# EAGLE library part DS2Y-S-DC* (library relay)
MINIATURE RELAY NAiS Source: http://www.mew-europe.com/.. en_ds_61005_0023.pdf
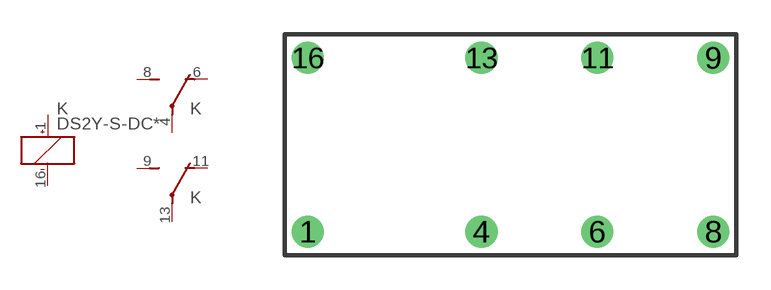
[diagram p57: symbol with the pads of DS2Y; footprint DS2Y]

Designator prefix K; gates 1=K+- 2=U 3=U

## DS2Y-S-DC1.5V (MPN: DS2Y-S-DC1.5V; OC_FARNELL: unknown; OC_NEWARK: 10C5827), DS2Y-S-DC3V (MPN: DS2Y-S-DC3V; OC_FARNELL: unknown; OC_NEWARK: 10C5832), DS2Y-S-DC5V (MPN: DS2Y-S-DC5V; OC_FARNELL: unknown; OC_NEWARK: 13P3268), DS2Y-S-DC6V (MPN: DS2Y-S-DC6V; OC_FARNELL: unknown; OC_NEWARK: 13P3271), DS2Y-S-DC9V (MPN: DS2Y-S-DC9V; OC_FARNELL: unknown; OC_NEWARK: 13P3272), DS2Y-S-DC12V (MPN: DS2Y-S-DC12V; OC_FARNELL: unknown; OC_NEWARK: 13P3261), DS2Y-S-DC24V (MPN: DS2Y-S-DC24V; OC_FARNELL: unknown; OC_NEWARK: 13P3264), DS2Y-S-DC48V (MPN: DS2Y-S-DC48V; OC_FARNELL: unknown; OC_NEWARK: 13P3267)  [DS2Y]
1  1:+  pas
4  2:P  pas
6  2:O  pas
8  2:S  pas
9  3:S  pas
11  3:O  pas
13  3:P  pas
16  1:-  pas

## Footprint DS2Y (pad centres in mm)
MINIATURE RELAY NAiS Source: http://www.mew-europe.com/.. en_ds_61005_0023.pdf
drill 0.9 round: 1 -8.89,-3.81; 4 -1.27,-3.81; 6 3.81,-3.81; 8 8.89,-3.81; 9 8.89,3.81; 11 3.81,3.81; 13 -1.27,3.81; 16 -8.89,3.81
